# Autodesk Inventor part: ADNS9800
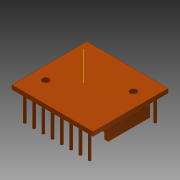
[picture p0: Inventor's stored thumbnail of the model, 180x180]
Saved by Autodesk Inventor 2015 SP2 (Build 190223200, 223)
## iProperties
Created: 2015-10
Part Number: ADNS9800
Material: Phenolharz
Document SubType Name: Modeling
Designer: rYan
Mass: 0.618105 g
Surface Area: 8.52157 cm^2
Volume: 0.447902 cm^3
Density: 1.38 g/cm^3
Appearance: Glatt - hellorange
Author: rYan
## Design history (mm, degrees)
sketch "Skizze1"
  geometry: L1 (-7.8, 7.2)-(7.8, 7.2); L2 (7.8, 7.2)-(7.8, -7.2); L3 (7.8, -7.2)-(-7.8, -7.2); L4 (-7.8, -7.2)-(-7.8, 7.2); L5 (0, 10.08)-(0, -10.08) reference; L6 (-10.92, 0)-(10.92, 0) reference; C1 r 0.65 at (5, 3.35); C2 r 0.65 at (-5.29, -3.2); 1 further point
  constraints: 8 end point, 2 centre point, 2 parallel, 1 horizontal, 1 perpendicular, 2 other
  dimensions: "d0" = 15.6 distance of L1.start L1.end; "d1" = 14.4 distance of L3.end L1.start; "d2" = 1.3 diameter of C1; "d3" = 1.3 diameter of C2; "d4" = 6.55 vertical distance of C1.centre C2.centre; "d5" = 10.29 horizontal distance of C1.centre C2.centre; "d6" = 2.8 distance from line of C1.centre L2; "d7" = 3.35 distance from line of C1.centre L6
extrude "Extrusion1" new body sketch "Skizze1" distance "d8" = 0.8; taper "d9" = 0 deg
sketch "Skizze2"
  geometry: L1 (0, -10.08)-(0, 10.08) reference; L2 (-10.92, 0)-(10.92, 0) reference; L3 (7.8, -7.2)-(7.8, 7.2) reference; C1 r 0.25 at (6.23, -6.3); 1 further point
  constraints: 1 centre point
  dimensions: "d10" = 0.5 diameter of C1; "d11" = 6.3 distance from line of C1.centre L2; "d12" = 1.57 distance from line of C1.centre L3
extrude "Extrusion2" join sketch "Skizze2" distance "d13" = 5.15; taper "d14" = 0 deg
pattern_linear "Rechteckige Anordnung1" dims "d17" = 1.78, "d20" = 12.6
sketch "Skizze3"
  geometry: L1 (0, -10.08)-(0, 10.08) reference; L2 (-10.92, 0)-(10.92, 0) reference; L3 (7.5, -4)-(6.8, -4); L4 (6.8, -4)-(6.8, 4); L5 (6.8, 4)-(7.5, 4); L6 (7.5, 4)-(7.5, -4); L7 (-6.8, -4)-(-7.5, -4); L8 (-7.5, -4)-(-7.5, 4); L9 (-7.5, 4)-(-6.8, 4); L10 (-6.8, 4)-(-6.8, -4); 1 further point
  constraints: 16 end point, 4 parallel, 2 horizontal, 2 perpendicular, 5 other
  dimensions: "d21" = 8 distance of L5.end L3.start; "d22" = 0.7 distance of L3.start L3.end; "d23" = 6.8 distance between parallel lines of L1 L4
extrude "Extrusion3" join sketch "Skizze3" distance "d24" = 2.6; taper "d25" = 0 deg
sketch "Skizze4"
  geometry: L1 (6.6, -2.2)-(6.6, 2.4); L2 (5.1, 3.9)-(-2.4, 3.9); L3 (-2.4, 3.9)-(-2.4, 3); L4 (-2.9, 2.5)-(-6.6, 2.5); L5 (-6.6, 2.5)-(-6.6, -2.5); L6 (-6.6, -2.5)-(-2.4, -2.5); L7 (-2.4, -2.5)-(-2.4, -3.9); L8 (-2.4, -3.9)-(4.29, -3.9); L9 (6.6, -2.2)-(5.29, -2.2); L10 (4.29, -3.9)-(4.29, -3.2); L11 (6.8, 4)-(6.8, -4) reference; L12 (-6.8, -4)-(-6.8, 4) reference; L13 (-10.92, 0)-(10.92, 0) reference; C1 r 0.65 at (5.29, -3.2) reference; A1 r 1.5 centre (5.1, 2.4) between (6.6, 2.4) and (5.1, 3.9); A2 r 0.5 centre (-2.9, 3) between (-2.9, 2.5) and (-2.4, 3); A3 r 1 centre (5.29, -3.2) between (5.29, -2.2) and (4.29, -3.2); 1 further point
  constraints: 20 end point, 6 point on circle, 6 tangent, 5 perpendicular, 3 centre point, 3 horizontal, 2 vertical, 1 coincident, 1 collinear, 2 other
  dimensions: "d26" = 0.2 distance between parallel lines of L1 L11; "d27" = 0.2 distance between parallel lines of L5 L12; "d28" = 7.8 distance between parallel lines of L2 L8; "d29" = 1 radius of A3; "d30" = 4.2 distance of L5.end L6.end; "d31" = 0.5 radius of A2; "d32" = 5 distance between parallel lines of L4 L6; "d33" = 1.5 radius of A1
extrude "Extrusion4" join sketch "Skizze4" distance "d34" = 2.2; taper "d35" = 0 deg
sketch "Skizze5"
  geometry: L1 (-10.92, 0)-(10.92, 0) reference; L2 (-7.8, 7.2)-(-7.8, -7.2) reference; C1 r 2 at (1.21, 0); C2 r 0.25 at (6.23, -6.3) reference; C3 r 1.3 at (-3.6, 0); C4 r 0.2 at (1.21, 0); C5 r 0.2 at (-3.6, 0); 1 further point
  constraints: 4 centre point, 2 coincident, 2 point on line
  dimensions: "d36" = 4 diameter of C1; "d37" = 5.02 horizontal distance of C1.centre C2.centre; "d38" = 2.6 diameter of C3; "d39" = 4.2 distance from line of L2 C3.centre; "d40" = 0.4 diameter of C4; "d41" = 0.4 diameter of C5
extrude "Extrusion5" join sketch "Skizze5" distance "d42" = 1.9; taper "d43" = 0 deg
node "Optische Achse"
node "Volumenkörper1"
node "Projizierte Kontur1"
